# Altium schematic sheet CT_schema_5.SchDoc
size 293 x 258 mm
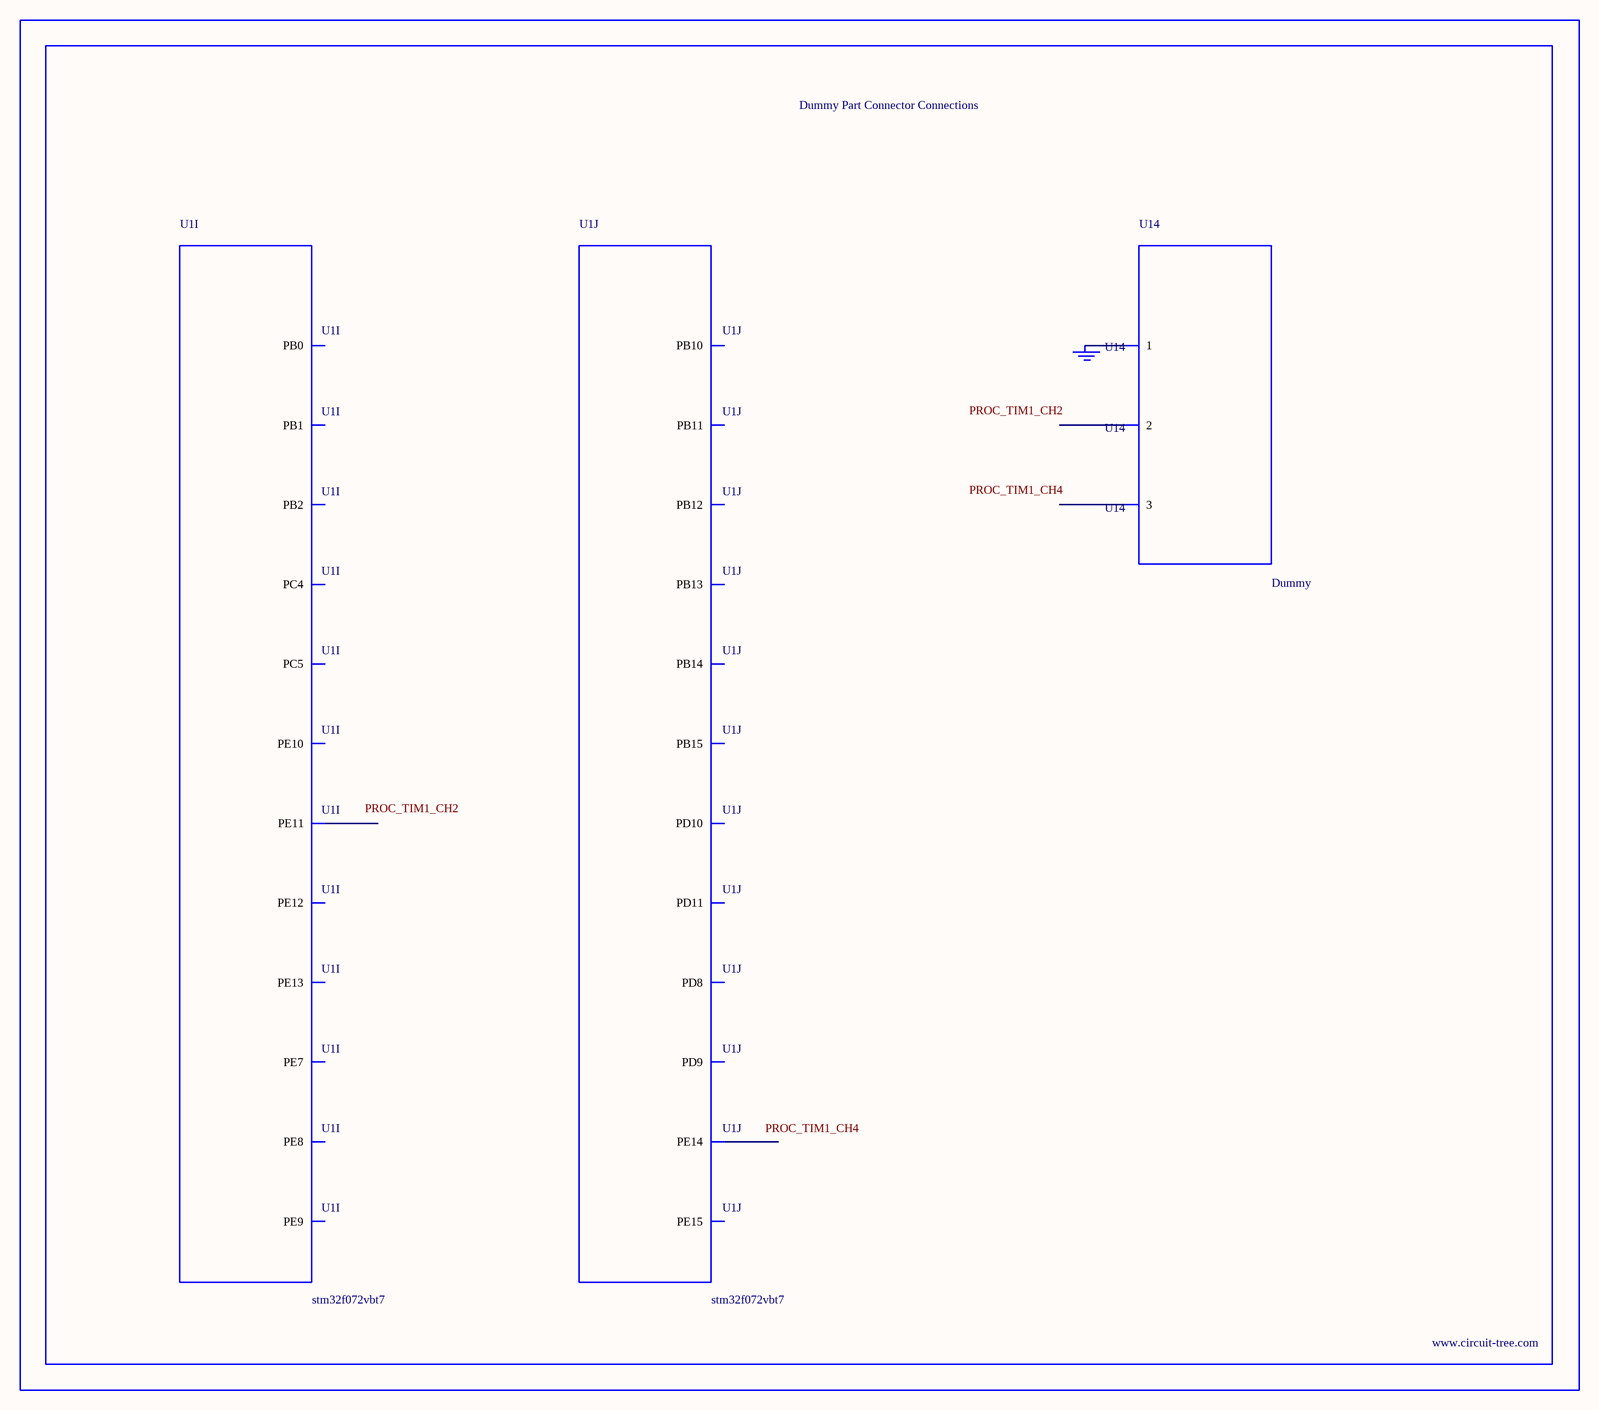
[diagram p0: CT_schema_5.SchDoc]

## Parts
BORDER4  (no value)
GND_INSTANCE_4_0  (no value)
U1  stm32f072vbt7  [LQFP100]  (parts I,J of 10)
U14  Dummy  [DUMMY_PACKAGE_115]

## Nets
NetGND_INSTANCE_4_0_0: GND_INSTANCE_4_0.0(GND) U14.1

Not connected (* = marked no-connect by the designer): U1 33(PC4) 34(PC5) 35(PB0) 36(PB1) 37(PB2) 38(PE7) 39(PE8) 40(PE9) 41(PE10) 42(PE11) 43(PE12) 44(PE13) 45(PE14) 46(PE15) 47(PB10) 48(PB11) 51(PB12) 52(PB13) 53(PB14) 54(PB15) 55(PD8) 56(PD9) 57(PD10) 58(PD11); U14 2 3

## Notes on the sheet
- Labels drawn without touching a wire or pin: PROC_TIM1_CH2, PROC_TIM1_CH4

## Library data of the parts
BORDER4 = BORDER_PAGE4
GND_INSTANCE_4_0 = GND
